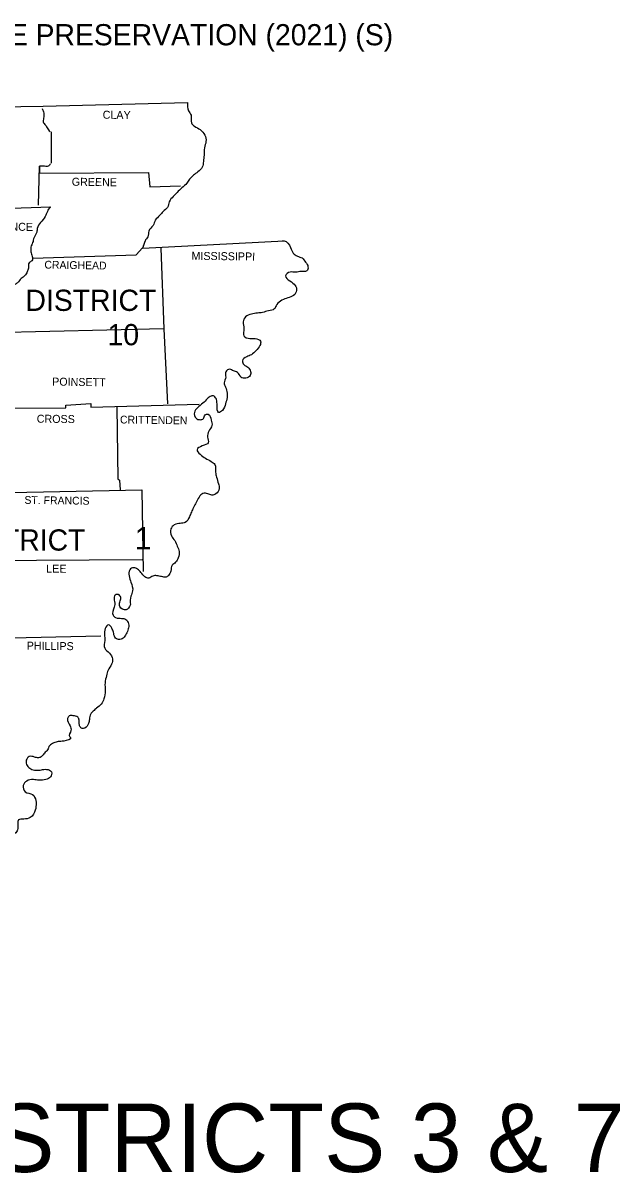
# Model space of a CAD drawing. Extents: x -43543 to 34500, y -13675 to 11152.
# Drawn here: x 15268 to 18405, y 4715 to 10759 of the extents above; entities that cross this region are included whole.
import ezdxf

# ---------------------------------------------------------------- set-up
doc = ezdxf.new("R2010")
doc.units = 0
for name, color, linetype in [('1', 7, 'Continuous'), ('2', 7, 'Continuous'), ('3', 7, 'Continuous'), ('R_Border', 7, 'Continuous')]:
    doc.layers.add(name, color=color, linetype=linetype)

msp = doc.modelspace()

# ---------------------------------------------------------------- linework, layer by layer
at = {"layer": '1'}
for p, q in [((15897.8, 9576.2), (15909.5, 9612.4)), ((15900.7, 9588), (15912.5, 9616.3))]:
    msp.add_line(p, q, dxfattribs=at)
for points in [[(10765.1, 10295.4), (12347.2, 10294.4), (13735.5, 10297.3), (15373.4, 10322.8), (16132.6, 10340.4)], [(15416.4, 10187.7), (15416.4, 10022.4)], [(15349.9, 9802.2), (15354.8, 10006.7), (15354.8, 9970.5), (15927.1, 9973.5), (15935, 9897.2), (16096.4, 9903)], [(15050.5, 9780.7), (15413.5, 9793.4)], [(15897.8, 9576.2), (16640.4, 9614.4)], [(15320.5, 9522.4), (15863.5, 9540), (15895.8, 9577.2)], [(15991.7, 9575.3), (16008.4, 9151.6), (16027.9, 8757.3)], [(16008.4, 9151.6), (15107.2, 9131.1)], [(15115.1, 8734.8), (15492.7, 8736.8), (15493.7, 8750.5), (15624.8, 8760.2), (15624.8, 8739.7), (16194.2, 8755.4)], [(15761.8, 8739.7), (15766.7, 8363), (15775.5, 8357.1), (15778.4, 8306.3)], [(15115.1, 8289.6), (15891.9, 8305.3)], [(15891.9, 8305.3), (15899.7, 7876.7)], [(15115.1, 7066.6), (15191.4, 7071.5), (15190.4, 7270.1), (15119, 7275), (15122.9, 7663.4), (15061.3, 7672.3), (15059.3, 7933.5), (15893.9, 7939.4)], [(15124.9, 7525.5), (15676.7, 7539.2)]]:
    msp.add_lwpolyline(points, dxfattribs=at)
for points in [[(16132.6, 10340.4), (16137.5, 10297.3), (16151.2, 10274.8), (16153.2, 10233.7), (16169.8, 10216.1), (16198.2, 10198.5), (16223.6, 10170.1), (16229.5, 10136.9), (16221.6, 10102.6), (16219.7, 10064.5), (16215.8, 10031.2), (16209.9, 10000.9), (16186.4, 9976.4), (16163.9, 9958.8), (16143.4, 9938.2), (16128.7, 9916.7), (16103.3, 9893.2), (16077.8, 9868.8), (16057.3, 9847.3), (16036.7, 9819.9), (16026.9, 9789.5), (16004.4, 9768), (15986.8, 9748.4), (15963.3, 9722), (15951.6, 9695.6), (15929.1, 9665.3), (15924.2, 9635.9), (15909.5, 9612.4), (15908.6, 9608.5)], [(15368.5, 10310), (15377.3, 10285.6), (15376.3, 10259.2), (15376.3, 10234.7), (15389, 10218.1), (15401.7, 10197.5), (15411.5, 10188.7)], [(15412.5, 10019.5), (15399.8, 10006.7), (15375.3, 10006.7), (15354.8, 10006.7)], [(15410.5, 9792.5), (15395.9, 9769), (15384.1, 9741.6), (15360.6, 9710.3), (15343, 9679.9), (15340.1, 9659.4), (15326.4, 9632), (15318.6, 9604.6), (15309.8, 9581.1), (15309.8, 9556.7), (15316.6, 9532.2), (15314.7, 9509.7), (15300, 9498.9), (15296.1, 9470.6), (15290.2, 9451), (15277.5, 9431.4), (15258.9, 9416.8), (15239.3, 9394.2), (15224.6, 9384.5)], [(16629.6, 9613.4), (16640.4, 9614.4), (16673.7, 9579.2), (16688.3, 9549.8), (16709.9, 9533.2), (16734.3, 9524.4), (16752.9, 9501.9), (16765.6, 9477.4), (16758.8, 9455.9), (16731.4, 9453.9), (16701.1, 9449), (16671.7, 9450), (16648.2, 9430.5), (16669.8, 9404), (16698.1, 9379.6), (16706, 9353.2), (16690.3, 9327.7), (16659, 9314), (16628.7, 9302.3), (16601.3, 9278.8), (16588.5, 9256.3), (16558.2, 9246.5), (16526.9, 9237.7), (16499.5, 9234.8), (16468.2, 9228.9), (16437.9, 9214.2), (16425.2, 9188.8), (16429.1, 9152.6), (16428.1, 9114.4), (16460.4, 9101.7), (16488.8, 9100.7), (16516.1, 9086.1), (16513.2, 9064.5), (16492.7, 9037.1), (16468.2, 9015.6), (16443.7, 9004.8), (16421.2, 8984.3), (16429.1, 8963.8), (16449.6, 8950.1), (16464.3, 8927.5), (16462.3, 8907), (16438.9, 8892.3), (16413.4, 8898.2), (16394.8, 8922.7), (16373.3, 8930.5), (16354.7, 8939.3), (16333.2, 8926.6), (16333.2, 8898.2), (16325.4, 8867.9), (16332.2, 8845.4), (16341, 8814.1), (16340, 8790.6), (16332.2, 8757.3), (16315.6, 8723.1), (16296, 8712.3), (16288.2, 8749.5), (16284.3, 8779.8), (16272.5, 8797.4), (16256.9, 8798.4), (16236.3, 8783.7), (16213.8, 8761.2), (16185.4, 8736.8), (16168.8, 8712.3), (16177.6, 8682), (16199.1, 8674.1), (16215.8, 8680), (16224.6, 8699.6), (16241.2, 8702.5), (16256.9, 8672.2)], [(16256.9, 8672.2), (16260.8, 8643.8), (16244.1, 8613.5), (16238.3, 8583.2), (16241.2, 8552.8), (16209.9, 8536.2), (16182.5, 8516.6), (16198.2, 8493.1), (16227.5, 8471.6), (16256.9, 8455), (16275.5, 8438.3), (16280.3, 8398.2), (16285.2, 8372.8), (16295, 8337.6), (16298.9, 8313.1), (16281.3, 8283.8), (16260.8, 8277.9), (16239.3, 8284.7), (16213.8, 8286.7), (16193.3, 8267.1), (16178.6, 8239.7), (16163.9, 8212.3), (16153.2, 8188.9), (16142.4, 8163.4), (16120.9, 8134.1), (16094.5, 8129.2), (16063.1, 8121.3), (16044.6, 8099.8), (16047.5, 8063.6), (16065.1, 8039.2), (16078.8, 8008.8), (16088.6, 7982.4), (16083.7, 7949.1), (16070, 7924.7), (16052.4, 7910), (16044.6, 7878.7), (16031.8, 7855.2), (16020.1, 7847.4), (15996.6, 7849.3), (15971.2, 7854.2), (15949.6, 7852.3), (15929.1, 7841.5), (15908.6, 7848.4), (15887, 7871.8), (15869.4, 7889.5), (15849.9, 7896.3), (15829.3, 7885.5), (15825.4, 7853.3), (15835.2, 7820), (15844, 7775), (15835.2, 7747.6), (15832.2, 7702.6)], [(15832.2, 7702.6), (15809.7, 7674.2), (15776.5, 7691.8), (15776.5, 7715.3), (15781.4, 7739.8), (15769.6, 7755.4), (15749.1, 7748.6), (15749.1, 7718.2), (15747.1, 7688.9), (15741.2, 7646.8), (15754.9, 7634.1), (15786.3, 7630.2), (15808.8, 7624.3), (15822.5, 7601.8), (15821.5, 7574.4), (15810.7, 7548), (15795.1, 7526.5), (15770.6, 7518.6), (15751, 7531.4), (15743.2, 7556.8), (15734.4, 7579.3), (15717.8, 7595.9), (15700.2, 7577.3), (15696.2, 7543.1), (15697.2, 7513.8), (15697.2, 7473.6), (15722.7, 7447.2), (15738.3, 7416.9), (15733.4, 7389.5), (15714.8, 7357.2), (15707, 7328.8), (15699.2, 7290.7), (15700.2, 7248.6), (15693.3, 7207.5), (15679.6, 7180.1), (15654.2, 7157.6), (15637.5, 7142.9), (15623.8, 7128.3), (15617, 7098.9), (15612.1, 7078.4), (15593.5, 7053.9), (15578.8, 7051.9), (15567.1, 7061.7), (15563.2, 7078.4), (15563.2, 7095), (15555.4, 7111.6), (15530.9, 7118.5), (15511.3, 7117.5), (15502.5, 7103.8), (15515.2, 7065.6), (15520.1, 7041.2), (15513.3, 7007.9), (15517.2, 7004), (15482, 6985.4), (15453.6, 6982.5), (15430.1, 6975.6), (15407.6, 6961), (15396.8, 6939.4), (15381.2, 6921.8), (15367.5, 6905.2), (15348.9, 6897.4), (15328.4, 6901.3), (15301, 6904.2), (15285.3, 6884.6), (15290.2, 6856.3), (15308.8, 6839.6), (15336.2, 6831.8), (15364.6, 6833.8), (15392, 6836.7), (15417.4, 6823), (15412.5, 6796.6), (15388, 6783.9), (15351.8, 6779.9), (15322.5, 6782.9), (15287.3, 6775.1), (15269.7, 6752.6), (15279.4, 6718.3), (15317.6, 6704.6), (15335.2, 6672.3), (15336.2, 6642), (15323.5, 6601.9), (15305.9, 6583.3), (15271.6, 6575.5), (15245.2, 6570.6), (15241.3, 6525.6), (15229.5, 6503.1), (15209, 6496.2), (15179.6, 6510.9), (15162, 6517.7), (15140.5, 6527.5), (15113.1, 6544.2), (15092.6, 6541.2), (15098.4, 6498.2), (15100.4, 6496.2), (15123.9, 6463.9), (15147.4, 6438.5), (15158.1, 6408.2)]]:
    msp.add_spline(points, degree=3, dxfattribs=at)

# ---------------------------------------------------------------- texts
msp.add_text('1', height=117.4, dxfattribs=at).set_placement((15855.7, 7993.2))
at = {"layer": '2'}
for s, height, rotation, p in [('CLAY', 42.06, 359.22578, (15686.5, 10256.2)), ('GREENE', 42.07, 359.2361, (15524, 9904)), ('LAWRENCE', 42.07, 359.26783, (15001.6, 9670.2)), ('MISSISSIPPI', 42.062, 359.30972, (16153.2, 9514.6)), ('CRAIGHEAD', 41.09, 359.11587, (15380.2, 9468.6)), ('POINSETT', 42.06, 359.19871, (15421, 8853.6)), ('CROSS', 42.06, 359.38394, (15340.1, 8658.5)), ('CRITTENDEN', 41.09, 359.21302, (15777.4, 8654.6)), ('ST. FRANCIS', 41.081, 359.22157, (15275.5, 8231.9)), ('LEE', 42.07, 359.43273, (15390, 7870.9)), ('PHILLIPS', 42.06, 359.31794, (15287.3, 7465.8))]:
    msp.add_text(s, height=height, rotation=rotation, dxfattribs=at).set_placement(p)
msp.add_text('ARKANSAS HIGHWAY DISTRICTS 3 & 7', height=360, dxfattribs=at).set_placement((9441.3, 4720.5))
at = {"layer": '3'}
for s, p in [('DISTRICT', (15280.9, 9245.9)), ('10', (15712, 9065.4)), ('DISTRICT', (14908.6, 7986.3))]:
    msp.add_text(s, height=111.54, dxfattribs=at).set_placement(p)
at = {"layer": 'R_Border'}
msp.add_text('DISTRICTS 3 & 7 BRIDGE PRESERVATION (2021) (S) ', height=111.378, dxfattribs=at).set_placement((13505.2, 10641.7))

doc.saveas('drawing.dxf')
